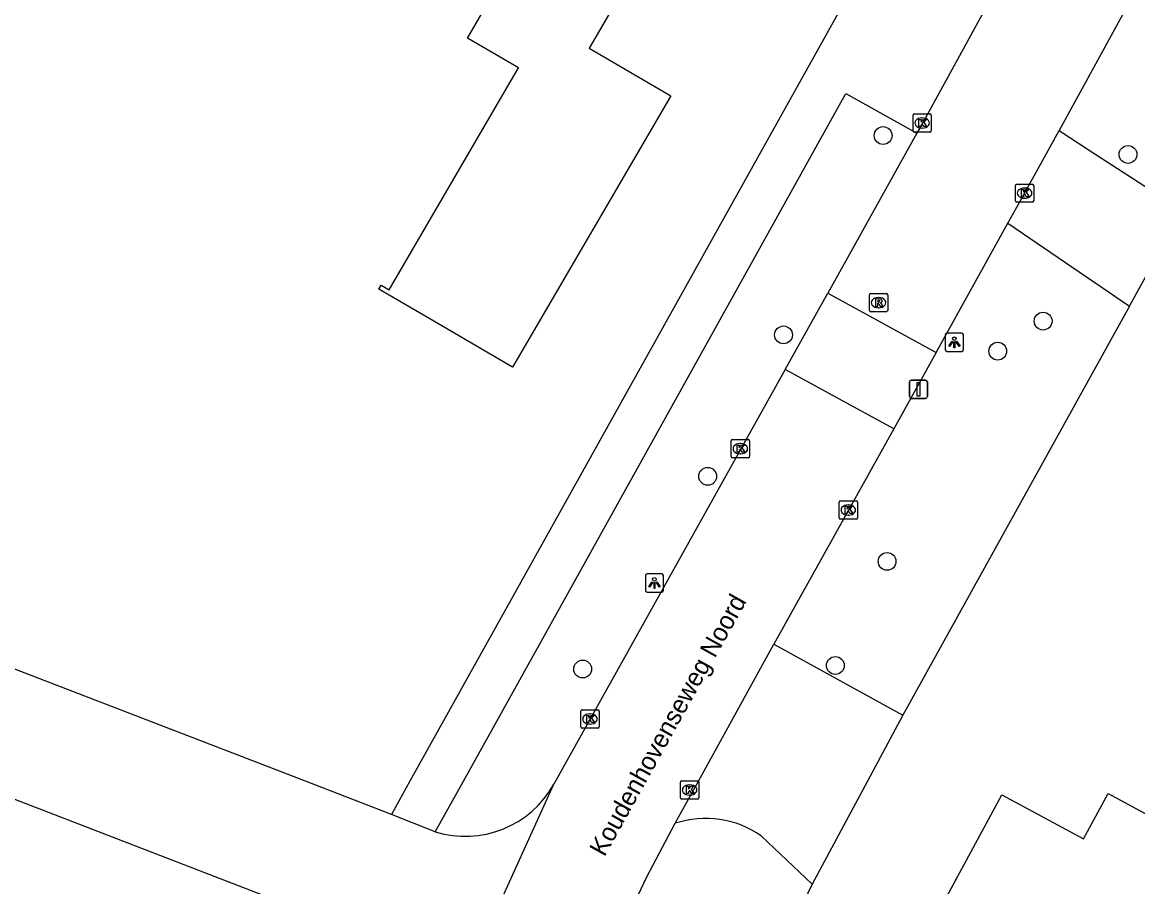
# Model space of a CAD drawing. Extents: x 162417 to 163721, y 384268 to 385416.
# Drawn here: x 163257.3 to 163318.6, y 385244.2 to 385291.7 of the extents above; entities that cross this region are included whole.
import ezdxf

# ---------------------------------------------------------------- set-up
doc = ezdxf.new("R2010")
doc.units = 0
for name, color, linetype in [('IMGEO_Afsluitpaal', 7, 'Continuous'), ('IMGEO_Boom', 7, 'Continuous'), ('IMGEO_Groenvoorziening', 7, 'Continuous'), ('IMGEO_Kolk', 7, 'Continuous'), ('IMGEO_Lichtpunt', 7, 'Continuous'), ('IMGEO_Openbare_ruimte_label', 7, 'Continuous'), ('IMGEO_Pand', 7, 'Continuous'), ('IMGEO_Rijbaan_lokaal_gesloten', 7, 'Continuous'), ('IMGEO_Rijbaan_lokaal_open', 7, 'Continuous'), ('IMGEO_Rioolput', 7, 'Continuous'), ('IMGEO_Voetpad_open', 7, 'Continuous')]:
    doc.layers.add(name, color=color, linetype=linetype)

msp = doc.modelspace()

# ---------------------------------------------------------------- linework, layer by layer
at = {"layer": 'IMGEO_Afsluitpaal'}
for p, q in [((163306.128, 385272.043), (163306.918, 385272.043)), ((163306.918, 385272.043), (163306.128, 385272.043)), ((163306.028, 385271.143), (163306.028, 385271.943)), ((163306.028, 385271.943), (163306.028, 385271.143)), ((163307.018, 385271.943), (163307.018, 385271.143)), ((163307.018, 385271.143), (163307.018, 385271.943)), ((163306.918, 385271.043), (163306.128, 385271.043)), ((163306.128, 385271.043), (163306.918, 385271.043))]:
    msp.add_line(p, q, dxfattribs=at)
msp.add_lwpolyline([(163306.448, 385271.918), (163306.598, 385271.918), (163306.598, 385271.168), (163306.448, 385271.168), (163306.448, 385271.918)], dxfattribs=at)
for centre, start, end in [((163306.128, 385271.943), 90, 180), ((163306.128, 385271.943), 90, 180), ((163306.918, 385271.943), 0, 90), ((163306.918, 385271.943), 360, 90), ((163306.128, 385271.143), 180, 270), ((163306.128, 385271.143), 180, 270), ((163306.918, 385271.143), 270, 0), ((163306.918, 385271.143), 270, 0)]:
    msp.add_arc(centre, 0.1, start, end, dxfattribs=at)
at = {"layer": 'IMGEO_Boom'}
for centre in [(163304.583, 385285.482), (163318.042, 385284.444), (163313.377, 385275.286), (163299.109, 385274.529), (163310.882, 385273.635), (163294.942, 385266.759), (163304.802, 385262.082), (163301.958, 385256.363), (163288.07, 385256.168)]:
    msp.add_circle(centre, 0.489, dxfattribs=at)
at = {"layer": 'IMGEO_Groenvoorziening'}
for points in [[(163318.117, 385276.112), (163305.659, 385253.628)], [(163300.69, 385244.351), (163295.052, 385232.686), (163292.438, 385226.695)]]:
    msp.add_lwpolyline(points, dxfattribs=at)
at = {"layer": 'IMGEO_Kolk'}
for p, q in [((163306.23, 385285.745), (163306.23, 385286.597)), ((163306.305, 385286.671), (163307.157, 385286.671)), ((163306.718, 385286.451), (163306.743, 385286.451)), ((163307.231, 385286.597), (163307.231, 385285.745)), ((163307.157, 385285.671), (163306.305, 385285.671)), ((163306.741, 385285.891), (163306.716, 385285.891)), ((163311.859, 385281.893), (163311.859, 385282.745)), ((163311.934, 385282.819), (163312.786, 385282.819)), ((163312.347, 385282.599), (163312.372, 385282.599)), ((163312.86, 385282.745), (163312.86, 385281.893)), ((163312.786, 385281.819), (163311.934, 385281.819)), ((163312.37, 385282.039), (163312.345, 385282.039)), ((163296.235, 385267.85), (163296.235, 385268.702)), ((163296.31, 385268.776), (163297.162, 385268.776)), ((163296.723, 385268.556), (163296.748, 385268.556)), ((163297.236, 385268.702), (163297.236, 385267.85)), ((163297.162, 385267.776), (163296.31, 385267.776)), ((163296.746, 385267.996), (163296.721, 385267.996)), ((163302.169, 385264.483), (163302.169, 385265.335)), ((163302.244, 385265.409), (163303.096, 385265.409)), ((163303.17, 385265.335), (163303.17, 385264.483)), ((163302.657, 385265.189), (163302.682, 385265.189)), ((163303.096, 385264.409), (163302.244, 385264.409)), ((163302.68, 385264.629), (163302.655, 385264.629)), ((163287.971, 385252.998), (163287.971, 385253.85)), ((163288.046, 385253.924), (163288.898, 385253.924)), ((163288.459, 385253.704), (163288.484, 385253.704)), ((163288.972, 385253.85), (163288.972, 385252.998)), ((163288.482, 385253.144), (163288.457, 385253.144)), ((163288.898, 385252.924), (163288.046, 385252.924)), ((163293.45, 385249.098), (163293.45, 385249.95)), ((163293.525, 385250.024), (163294.377, 385250.024)), ((163294.451, 385249.95), (163294.451, 385249.098)), ((163293.938, 385249.804), (163293.963, 385249.804)), ((163294.377, 385249.024), (163293.525, 385249.024)), ((163293.961, 385249.244), (163293.936, 385249.244))]:
    msp.add_line(p, q, dxfattribs=at)
for points in [[(163306.23, 385285.745), (163306.23, 385286.597)], [(163306.305, 385286.671), (163307.157, 385286.671)], [(163306.551, 385286.371), (163306.674, 385286.371), (163306.674, 385286.22), (163306.804, 385286.371), (163306.968, 385286.371), (163306.822, 385286.22), (163306.975, 385285.971), (163306.823, 385285.971), (163306.738, 385286.135), (163306.674, 385286.068), (163306.674, 385285.971), (163306.551, 385285.971), (163306.551, 385286.371)], [(163307.231, 385286.597), (163307.231, 385285.745)], [(163307.157, 385285.671), (163306.305, 385285.671)], [(163311.859, 385281.893), (163311.859, 385282.745)], [(163311.934, 385282.819), (163312.786, 385282.819)], [(163312.18, 385282.519), (163312.303, 385282.519), (163312.303, 385282.368), (163312.433, 385282.519), (163312.597, 385282.519), (163312.451, 385282.368), (163312.604, 385282.119), (163312.452, 385282.119), (163312.367, 385282.283), (163312.303, 385282.216), (163312.303, 385282.119), (163312.18, 385282.119), (163312.18, 385282.519)], [(163312.86, 385282.745), (163312.86, 385281.893)], [(163312.786, 385281.819), (163311.934, 385281.819)], [(163296.235, 385267.85), (163296.235, 385268.702)], [(163296.31, 385268.776), (163297.162, 385268.776)], [(163296.556, 385268.476), (163296.679, 385268.476), (163296.679, 385268.325), (163296.809, 385268.476), (163296.973, 385268.476), (163296.827, 385268.325), (163296.98, 385268.076), (163296.828, 385268.076), (163296.743, 385268.24), (163296.679, 385268.173), (163296.679, 385268.076), (163296.556, 385268.076), (163296.556, 385268.476)], [(163297.236, 385268.702), (163297.236, 385267.85)], [(163297.162, 385267.776), (163296.31, 385267.776)], [(163302.169, 385264.483), (163302.169, 385265.335)], [(163302.244, 385265.409), (163303.096, 385265.409)], [(163303.17, 385265.335), (163303.17, 385264.483)], [(163302.49, 385265.109), (163302.613, 385265.109), (163302.613, 385264.958), (163302.743, 385265.109), (163302.907, 385265.109), (163302.761, 385264.958), (163302.914, 385264.709), (163302.762, 385264.709), (163302.677, 385264.873), (163302.613, 385264.806), (163302.613, 385264.709), (163302.49, 385264.709), (163302.49, 385265.109)], [(163303.096, 385264.409), (163302.244, 385264.409)], [(163287.971, 385252.998), (163287.971, 385253.85)], [(163288.046, 385253.924), (163288.898, 385253.924)], [(163288.292, 385253.624), (163288.415, 385253.624), (163288.415, 385253.473), (163288.545, 385253.624), (163288.709, 385253.624), (163288.563, 385253.473), (163288.716, 385253.224), (163288.564, 385253.224), (163288.479, 385253.388), (163288.415, 385253.321), (163288.415, 385253.224), (163288.292, 385253.224), (163288.292, 385253.624)], [(163288.972, 385253.85), (163288.972, 385252.998)], [(163288.898, 385252.924), (163288.046, 385252.924)], [(163293.45, 385249.098), (163293.45, 385249.95)], [(163293.525, 385250.024), (163294.377, 385250.024)], [(163294.451, 385249.95), (163294.451, 385249.098)], [(163293.771, 385249.724), (163293.894, 385249.724), (163293.894, 385249.573), (163294.024, 385249.724), (163294.188, 385249.724), (163294.042, 385249.573), (163294.195, 385249.324), (163294.043, 385249.324), (163293.958, 385249.488), (163293.894, 385249.421), (163293.894, 385249.324), (163293.771, 385249.324), (163293.771, 385249.724)], [(163294.377, 385249.024), (163293.525, 385249.024)]]:
    msp.add_lwpolyline(points, dxfattribs=at)
for centre, start, end in [((163306.307, 385286.595), 91.55205, 178.44795), ((163306.307, 385286.595), 91.55205, 178.44795), ((163307.155, 385286.595), 1.55205, 88.44795), ((163307.155, 385286.595), 1.55205, 88.44795), ((163306.307, 385285.747), 181.55205, 268.44795), ((163306.307, 385285.747), 181.55205, 268.44795), ((163307.155, 385285.747), 271.55205, 358.44795), ((163307.155, 385285.747), 271.55205, 358.44795), ((163311.936, 385282.743), 91.55205, 178.44795), ((163311.936, 385282.743), 91.55205, 178.44795), ((163312.784, 385282.743), 1.55205, 88.44795), ((163312.784, 385282.743), 1.55205, 88.44795), ((163311.936, 385281.895), 181.55205, 268.44795), ((163311.936, 385281.895), 181.55205, 268.44795), ((163312.784, 385281.895), 271.55205, 358.44795), ((163312.784, 385281.895), 271.55205, 358.44795), ((163296.312, 385268.7), 91.55205, 178.44795), ((163296.312, 385268.7), 91.55205, 178.44795), ((163297.16, 385268.7), 1.55205, 88.44795), ((163297.16, 385268.7), 1.55205, 88.44795), ((163296.312, 385267.852), 181.55205, 268.44795), ((163296.312, 385267.852), 181.55205, 268.44795), ((163297.16, 385267.852), 271.55205, 358.44795), ((163297.16, 385267.852), 271.55205, 358.44795), ((163302.246, 385265.333), 91.55205, 178.44795), ((163302.246, 385265.333), 91.55205, 178.44795), ((163303.094, 385265.333), 1.55205, 88.44795), ((163303.094, 385265.333), 1.55205, 88.44795), ((163302.246, 385264.485), 181.55205, 268.44795), ((163302.246, 385264.485), 181.55205, 268.44795), ((163303.094, 385264.485), 271.55205, 358.44795), ((163303.094, 385264.485), 271.55205, 358.44795), ((163288.048, 385253.848), 91.55205, 178.44795), ((163288.048, 385253.848), 91.55205, 178.44795), ((163288.896, 385253.848), 1.55205, 88.44795), ((163288.896, 385253.848), 1.55205, 88.44795), ((163288.048, 385253), 181.55205, 268.44795), ((163288.048, 385253), 181.55205, 268.44795), ((163288.896, 385253), 271.55205, 358.44795), ((163288.896, 385253), 271.55205, 358.44795), ((163293.527, 385249.948), 91.55205, 178.44795), ((163293.527, 385249.948), 91.55205, 178.44795), ((163294.375, 385249.948), 1.55205, 88.44795), ((163294.375, 385249.948), 1.55205, 88.44795), ((163293.527, 385249.1), 181.55205, 268.44795), ((163293.527, 385249.1), 181.55205, 268.44795), ((163294.375, 385249.1), 271.55205, 358.44795), ((163294.375, 385249.1), 271.55205, 358.44795)]:
    msp.add_arc(centre, 0.0765, start, end, dxfattribs=at)
for centre, major_axis, ratio, start_param, end_param in [((163306.717, 385286.171), (-0.387, 0.002), 0.722429, 4.712389, 7.853982), ((163306.742, 385286.171), (-0.39, 0.002), 0.717154, 1.570796, 4.712389), ((163312.346, 385282.319), (-0.387, 0.002), 0.722429, 4.712389, 7.853982), ((163312.371, 385282.319), (-0.39, 0.002), 0.717154, 1.570796, 4.712389), ((163296.722, 385268.276), (-0.387, 0.002), 0.722429, 4.712389, 7.853982), ((163296.747, 385268.276), (-0.39, 0.002), 0.717154, 1.570796, 4.712389), ((163302.656, 385264.909), (-0.387, 0.002), 0.722429, 4.712389, 7.853982), ((163302.681, 385264.909), (-0.39, 0.002), 0.717154, 1.570796, 4.712389), ((163288.458, 385253.424), (-0.387, 0.002), 0.722429, 4.712389, 7.853982), ((163288.483, 385253.424), (-0.39, 0.002), 0.717154, 1.570796, 4.712389), ((163293.937, 385249.524), (-0.387, 0.002), 0.722429, 4.712389, 7.853982), ((163293.962, 385249.524), (-0.39, 0.002), 0.717154, 1.570796, 4.712389)]:
    msp.add_ellipse(centre, major_axis=major_axis, ratio=ratio, start_param=start_param, end_param=end_param, dxfattribs=at)
at = {"layer": 'IMGEO_Lichtpunt'}
for p, q in [((163307.999, 385274.524), (163307.999, 385273.717)), ((163307.999, 385274.524), (163307.999, 385273.717)), ((163308.901, 385274.619), (163308.093, 385274.619)), ((163308.901, 385274.619), (163308.093, 385274.619)), ((163308.995, 385273.717), (163308.995, 385274.524)), ((163308.995, 385273.717), (163308.995, 385274.524)), ((163308.093, 385273.623), (163308.901, 385273.623)), ((163308.093, 385273.623), (163308.901, 385273.623)), ((163291.516, 385261.3), (163291.516, 385260.493)), ((163291.516, 385261.3), (163291.516, 385260.493)), ((163292.418, 385261.395), (163291.61, 385261.395)), ((163292.418, 385261.395), (163291.61, 385261.395)), ((163292.512, 385260.493), (163292.512, 385261.3)), ((163292.512, 385260.493), (163292.512, 385261.3)), ((163291.61, 385260.399), (163292.418, 385260.399)), ((163291.61, 385260.399), (163292.418, 385260.399))]:
    msp.add_line(p, q, dxfattribs=at)
for points in [[(163308.373, 385274.188), (163308.412, 385274.16), (163308.224, 385273.898), (163308.186, 385273.925), (163308.373, 385274.188)], [(163308.475, 385274.14), (163308.522, 385274.14), (163308.522, 385273.818), (163308.475, 385273.818), (163308.475, 385274.14)], [(163308.585, 385274.16), (163308.623, 385274.187), (163308.81, 385273.925), (163308.771, 385273.897), (163308.585, 385274.16)], [(163291.89, 385260.964), (163291.929, 385260.936), (163291.741, 385260.674), (163291.703, 385260.701), (163291.89, 385260.964)], [(163292.102, 385260.936), (163292.14, 385260.963), (163292.327, 385260.701), (163292.288, 385260.673), (163292.102, 385260.936)], [(163291.992, 385260.916), (163292.039, 385260.916), (163292.039, 385260.594), (163291.992, 385260.594), (163291.992, 385260.916)]]:
    msp.add_lwpolyline(points, dxfattribs=at)
for centre in [(163308.498, 385274.322), (163292.015, 385261.098)]:
    msp.add_circle(centre, 0.0994, dxfattribs=at)
for centre, start, end in [((163308.093, 385274.524), 90, 180), ((163308.093, 385274.524), 90, 180), ((163308.901, 385274.524), 0, 90), ((163308.901, 385274.524), 0, 90), ((163308.093, 385273.717), 180, 270), ((163308.093, 385273.717), 180, 270), ((163308.901, 385273.717), 270, 0), ((163308.901, 385273.717), 270, 360), ((163291.61, 385261.3), 90, 180), ((163291.61, 385261.3), 90, 180), ((163292.418, 385261.3), 0, 90), ((163292.418, 385261.3), 0, 90), ((163291.61, 385260.493), 180, 270), ((163291.61, 385260.493), 180, 270), ((163292.418, 385260.493), 270, 0), ((163292.418, 385260.493), 270, 360)]:
    msp.add_arc(centre, 0.0946, start, end, dxfattribs=at)
at = {"layer": 'IMGEO_Pand'}
for points in [[(163271.934, 385300.031), (163273.678, 385303.02), (163276.197, 385307.338), (163292.739, 385297.685), (163292.512, 385297.296), (163288.42, 385290.282), (163292.911, 385287.661), (163284.217, 385272.761), (163279.899, 385275.28), (163276.875, 385277.044), (163277, 385277.259), (163277.431, 385277.007), (163284.546, 385289.202), (163281.738, 385290.839), (163283.249, 385293.43), (163271.934, 385300.031)], [(163324.662, 385230.824), (163322.342, 385232.08), (163322.742, 385232.817), (163321.153, 385233.677), (163320.783, 385232.993), (163318.546, 385234.204), (163319.401, 385235.784), (163313.666, 385238.888), (163309.631, 385231.43), (163308.032, 385232.296), (163303.634, 385234.676), (163306.706, 385240.352), (163306.379, 385240.528), (163311.105, 385249.261), (163315.593, 385246.832), (163316.945, 385249.331), (163321.343, 385246.951), (163330.661, 385241.908), (163324.662, 385230.824)]]:
    msp.add_lwpolyline(points, dxfattribs=at)
at = {"layer": 'IMGEO_Rijbaan_lokaal_gesloten'}
for points in [[(163319.219, 385294.694), (163317.937, 385292.488), (163314.257, 385285.753)], [(163310.144, 385292.344), (163306.692, 385286.048), (163306.445, 385285.606)], [(163306.445, 385285.606), (163301.538, 385276.816)], [(163311.438, 385280.665), (163311.932, 385281.554), (163313.748, 385284.822), (163314.257, 385285.753)], [(163277.559, 385248.179), (163272.829, 385250), (163230.586, 385266.263), (163184.131, 385283.914)], [(163274.704, 385242.119), (163254.239, 385250), (163172.476, 385281.443)], [(163307.496, 385273.57), (163311.438, 385280.665)], [(163299.198, 385272.624), (163286.569, 385250), (163286.477, 385249.835)], [(163305.165, 385269.374), (163298.585, 385257.53)], [(163293.157, 385247.691), (163294.431, 385250), (163298.585, 385257.53)], [(163279.27, 385233.939), (163286.477, 385249.835)], [(163279.966, 385247.222), (163277.559, 385248.179)], [(163285.042, 385229.499), (163286.305, 385232.911), (163288.581, 385238.329), (163291.581, 385244.718), (163293.157, 385247.691)]]:
    msp.add_lwpolyline(points, dxfattribs=at)
msp.add_arc((163281.613, 385252.537), 5.564, 252.78567, 330.94757, dxfattribs=at)
at = {"layer": 'IMGEO_Rijbaan_lokaal_open'}
for points in [[(163299.198, 385272.624), (163301.538, 385276.816)], [(163301.538, 385276.816), (163307.496, 385273.57)], [(163307.496, 385273.57), (163305.165, 385269.374)], [(163305.165, 385269.374), (163299.198, 385272.624)]]:
    msp.add_lwpolyline(points, dxfattribs=at)
at = {"layer": 'IMGEO_Rioolput'}
for p, q in [((163303.834, 385275.876), (163303.834, 385276.728)), ((163303.909, 385276.802), (163304.761, 385276.802)), ((163304.322, 385276.582), (163304.347, 385276.582)), ((163304.835, 385276.728), (163304.835, 385275.876)), ((163304.761, 385275.802), (163303.909, 385275.802)), ((163304.345, 385276.022), (163304.32, 385276.022))]:
    msp.add_line(p, q, dxfattribs=at)
for points in [[(163303.834, 385275.876), (163303.834, 385276.728)], [(163303.909, 385276.802), (163304.761, 385276.802)], [(163304.423, 385276.5), (163304.171, 385276.502), (163304.171, 385276.102)], [(163304.349, 385276.421), (163304.295, 385276.421), (163304.295, 385276.34)], [(163304.295, 385276.34), (163304.347, 385276.34)], [(163304.835, 385276.728), (163304.835, 385275.876)], [(163304.761, 385275.802), (163303.909, 385275.802)], [(163304.171, 385276.102), (163304.295, 385276.102), (163304.295, 385276.264), (163304.306, 385276.264)], [(163304.353, 385276.235), (163304.424, 385276.102), (163304.564, 385276.102), (163304.499, 385276.228)]]:
    msp.add_lwpolyline(points, dxfattribs=at)
for centre, radius, start, end in [((163303.911, 385276.726), 0.0765, 91.55205, 178.44795), ((163303.911, 385276.726), 0.0765, 91.55205, 178.44795), ((163304.331, 385276.529), 0.19, 274.7715, 282.96867), ((163304.355, 385276.325), 0.0964, 77.00612, 93.18647), ((163304.369, 385276.382), 0.0378, 276.66336, 79.67722), ((163304.422, 385276.39), 0.109, 350.36119, 89.41601), ((163304.42, 385276.39), 0.112, 277.58423, 350.98172), ((163304.759, 385276.726), 0.0765, 1.55205, 88.44795), ((163304.759, 385276.726), 0.0765, 1.55205, 88.44795), ((163303.911, 385275.878), 0.0765, 181.55205, 268.44795), ((163303.911, 385275.878), 0.0765, 181.55205, 268.44795), ((163304.305, 385276.211), 0.0533, 26.02933, 88.69889), ((163304.404, 385276.175), 0.108, 29.51342, 73.79051), ((163304.759, 385275.878), 0.0765, 271.55205, 358.44795), ((163304.759, 385275.878), 0.0765, 271.55205, 358.44795)]:
    msp.add_arc(centre, radius, start, end, dxfattribs=at)
for centre, major_axis, ratio, start_param, end_param in [((163304.321, 385276.302), (-0.387, 0.002), 0.722429, 4.712389, 7.853982), ((163304.346, 385276.302), (-0.39, 0.002), 0.717154, 1.570796, 4.712389)]:
    msp.add_ellipse(centre, major_axis=major_axis, ratio=ratio, start_param=start_param, end_param=end_param, dxfattribs=at)
at = {"layer": 'IMGEO_Voetpad_open'}
for points in [[(163307.686, 385302.216), (163278.574, 385250), (163277.559, 385248.179)], [(163279.966, 385247.222), (163281.514, 385250), (163302.53, 385287.792), (163306.445, 385285.606)], [(163314.257, 385285.753), (163315.967, 385284.647), (163321.031, 385281.372)], [(163318.117, 385276.112), (163318.656, 385277.086), (163320.515, 385280.446), (163321.031, 385281.372)], [(163311.438, 385280.665), (163318.117, 385276.112)], [(163298.585, 385257.53), (163305.659, 385253.628)], [(163305.659, 385253.628), (163303.716, 385250), (163300.69, 385244.351)], [(163300.69, 385244.351), (163297.893, 385246.987)]]:
    msp.add_lwpolyline(points, dxfattribs=at)
msp.add_arc((163294.832, 385242.677), 5.286, 54.6158, 108.47414, dxfattribs=at)

# ---------------------------------------------------------------- texts
at = {"layer": 'IMGEO_Openbare_ruimte_label'}
msp.add_text('Koudenhovenseweg Noord', height=1, rotation=60.92314, dxfattribs=at).set_placement((163289.266, 385245.809))

doc.saveas('drawing.dxf')
